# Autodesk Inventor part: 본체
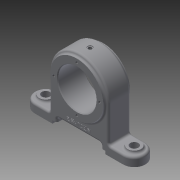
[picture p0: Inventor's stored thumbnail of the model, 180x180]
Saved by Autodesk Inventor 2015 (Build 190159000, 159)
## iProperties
Created: 2019-05
Part Number: 본체
Material: 알루미늄 6061
Document SubType Name: Modeling
Designer: 10403
Density: 2.7 g/cm^3
Appearance: 기본값
Mass: 454.389 g
Surface Area: 318.676 cm^2
Volume: 168.292 cm^3
Author: 10403
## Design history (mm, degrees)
sketch "스케치1"
  geometry: C1 r 40 at (0, 0); 1 further point
  constraints: 1 centre point, 1 coincident
  dimensions: "d0" = 80 diameter of C1
extrude "돌출1" new body sketch "스케치1" stored distance "d1" = 36; taper "d2" = 0 deg
sketch "스케치2"
  geometry: C1 r 40 at (0, 0) reference; C2 r 36 at (0, 0)
  constraints: 1 centre point, 1 coincident
  dimensions: "d3" = 72 diameter of C2
extrude "돌출2" cut sketch "스케치2" distance "d4" = 3; taper "d5" = 0 deg
sketch "스케치3"
  geometry: C1 r 36 at (0, 0) reference
hole "구멍1" sketch "스케치3" at (0, 0) diameter "d6" = 52; stored, may be unused: countersink angle "d10" = 90 deg, drill point angle "d12" = 118 deg; dims "d7" = 6, "d8" = 4, "d9" = 2, "d11" = 8
sketch "스케치4"
  geometry: L1 (75, -48)-(-75, -48); L2 (-75, -48)-(-75, -60); L3 (-75, -60)-(75, -60); L4 (75, -60)-(75, -48); C1 r 26 at (0, 0) reference; C2 r 40 at (0, 0) reference; 2 further points
  constraints: 8 end point, 2 parallel, 1 horizontal, 1 midpoint, 1 perpendicular, 1 vertical alignment
  dimensions: "d13" = 150 distance of L2.end L3.end; "d14" = 12 distance between parallel lines of L1 L3; "d15" = 60 distance from line of L3 point (0, 0)
extrude "돌출3" join sketch "스케치4" stored distance "d16" = 30; taper "d17" = 0 deg
fillet "모깎기1" dims "d18" = 15
sketch "스케치5"
  geometry: C1 r 9 at (0, -15); A1 r 15 centre (0, -15) between (0, 0) and (0, -30) reference; 1 further point
  constraints: 1 centre point, 1 coincident
  dimensions: "d19" = 18 diameter of C1
extrude "돌출4" join sketch "스케치5" distance "d20" = 3; taper "d21" = 0 deg
sketch "스케치6"
  geometry: C1 r 9 at (0, 0) reference; 1 further point
hole "구멍2" sketch "스케치6" at (0, 0) diameter "d22" = 11; stored, may be unused: countersink angle "d26" = 90 deg, drill point angle "d28" = 118 deg; dims "d23" = 6, "d24" = 4, "d25" = 2, "d27" = 8
sketch "스케치7"
  geometry: L1 (0, 0)-(120, 0) reference; L2 (20, -30)-(100, -30); L3 (100, -30)-(100, 0); L4 (100, 0)-(20, 0); L5 (20, 0)-(20, -30); L6 (20, -30)-(100, 0); L7 (100, -30)-(20, 0); 1 further point
  constraints: 12 end point, 2 midpoint, 2 parallel, 1 horizontal, 1 perpendicular, 1 point on line
  dimensions: "d29" = 40 distance from line of point (60, -15) L5
extrude "돌출5" join sketch "스케치7" stored distance "d30" = 3; taper "d31" = 0 deg
sketch "스케치8"
  geometry: L1 (-60, -60)-(60, -60) reference; L2 (-36, -56)-(36, -56); L3 (36, -56)-(36, -60); L4 (36, -60)-(-36, -60); L5 (-36, -60)-(-36, -56); 1 further point
  constraints: 8 end point, 2 midpoint, 2 parallel, 1 horizontal, 1 perpendicular
  dimensions: "d32" = 72 distance of L2.start L2.end; "d33" = 4 distance between parallel lines of L2 L1
extrude "돌출6" cut sketch "스케치8" stored distance "d34" = 3; taper "d35" = 0 deg
sketch "스케치9"
  geometry: L1 (-36, -56)-(36, -56) reference; L2 (-30, -50)-(30, -50); L3 (30, -50)-(30, -56); L4 (30, -56)-(-30, -56); L5 (-30, -56)-(-30, -50); 1 further point
  constraints: 8 end point, 2 midpoint, 2 parallel, 1 horizontal, 1 perpendicular
  dimensions: "d36" = 60 distance of L2.start L2.end; "d37" = 6 distance between parallel lines of L4 L2
extrude "돌출7" cut sketch "스케치9" stored distance "d38" = 3; taper "d39" = 0 deg
sketch "스케치10"
  geometry: C1 r 26 at (0, 0) reference; 1 further point
  constraints: 1 vertical alignment
  dimensions: "d40" = 31 distance of C1.centre point (0, 31)
hole "구멍3" sketch "스케치10" at (0, 31) diameter "d41" = 3.242; stored, may be unused: countersink angle "d45" = 90 deg, drill point angle "d47" = 118 deg; dims "d42" = 6, "d43" = 4, "d44" = 2, "d46" = 8
node "작업 평면1"
sketch "스케치11"
  geometry: 1 further point
hole "구멍4" sketch "스케치11" at (60, 0) diameter "d52" = 4.917; stored, may be unused: countersink angle "d56" = 90 deg, drill point angle "d58" = 118 deg; dims "d53" = 8, "d54" = 7, "d55" = 1, "d57" = 10
sketch "스케치12"
  geometry: C1 r 1 at (60, 0); 1 further point
  constraints: 1 centre point, 1 coincident
  dimensions: "d59" = 2 diameter of C1
extrude "돌출8" cut sketch "스케치12" distance "d60" = 40; taper "d61" = 0 deg
sketch "스케치13"
  geometry: L1 (-30, -50)-(30, -50) reference; A1 r 40 centre (0, 0) between (40, 0) and (-40, 0) reference; 1 further point
  constraints: 1 vertical alignment, 1 other
  dimensions: "d62" = 7 distance from line of point (0, -43) L1
feature "엠보싱1" sketch "스케치13" dims "d13" = 150, "d14" = 12, "d15" = 60, "d63" = 0.5, "d64" = 0
fillet "모깎기2" dims "d65" = 3
fillet "모깎기3" dims "d66" = 3
fillet "모깎기4" dims "d67" = 3
fillet "모깎기5" dims "d68" = 3
fillet "모깎기6" dims "d69" = 3
fillet "모깎기7" dims "d70" = 3
fillet "모깎기8" dims "d71" = 3
chamfer "모따기1" distance "d72" = 1; stored, may be unused: second distance "d73" = 2, angle "d74" = 45 deg
sketch "스케치14"
  geometry: C1 r 1.5 at (0, 26); A1 r 36 centre (0, 0) between (34.154, -11.38) and (-34.154, -11.38) reference; 2 further points
  constraints: 3 vertical alignment, 1 centre point, 2 other
  dimensions: "d75" = 3 diameter of C1
extrude "돌출9" cut sketch "스케치14" stored distance "d76" = 10; taper "d77" = 0 deg
node "솔리드1"
mirror "대칭1"
mirror "대칭2"
pattern_circular "원형 패턴1" dims angle "d49" = 360 deg
mirror "대칭3"
node "절단 모서리 투영1"
